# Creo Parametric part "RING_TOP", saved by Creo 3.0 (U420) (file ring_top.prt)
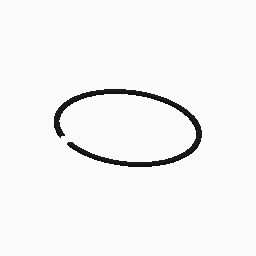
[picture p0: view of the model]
Units: millimeter Kilogram Sec (mmKs); MM, KILOGRAM, SECS

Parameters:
  MATERIAL = "GOE 52"

Created from: INLBS_PART_SOLID.PRT

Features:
  1. coordinate system "ORIGIN"
  2. datum plane "SIDE", "RIGHT"
  3. datum plane "DTM1", "TOP"
  4. datum plane "DTM2", "FRONT"
  5. datum axis "RING_AXIS"
  6. extrusion "Extrude 1"
  7. extruded cut "Extrude 2"

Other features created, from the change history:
  group "COPIED_GROUP"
